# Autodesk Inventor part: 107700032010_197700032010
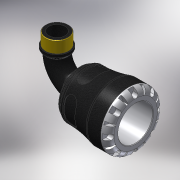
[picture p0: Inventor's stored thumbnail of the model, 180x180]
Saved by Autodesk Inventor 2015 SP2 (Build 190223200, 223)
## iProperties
Created: 2016-12
Part Number: 107700032010_197700032010
Material: PVC-Piping
Description: PLASSON 90° ELBOW WITH MALE INTEGRAL BRASS 32X1" SERIES 1
Document SubType Name: Modeling
Designer: KIM
Mass: 664.223 g
Surface Area: 733.008 cm^2
Volume: 474.445 cm^3
Density: 1.4 g/cm^3
Appearance: Black Cast
Author: KIM
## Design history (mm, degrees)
derived "1077.ipt"
feature "Solid1::1077.ipt"
tag "TaggingFeature1"
body "Solid1"
other parameters: "d1" = 22.68, "d2" = 32, "d4" = 58, "d8" = 49.3, "d13" = 7.2, "d14" = 7.2, "d15" = 0, "d17" = 360 deg, "d19" = 8 deg, "d20" = 0.64, "d21" = 0.64, "d22" = 8 deg, "d24" = 0, "d26" = 360 deg, "d33" = 5.8, "d43" = 45.24, "d51" = 0.58, "d54" = 11.2, "d55" = 7.04, "d57" = 14.112, "d58" = 0, "d74" = 0, "d78" = 54, "d82" = 0.64, "d115" = 360 deg, "d207" = 90 deg, "d228" = 9.52, "d247" = 1.16, "d248" = 3.24, "d268" = 27.115, "d269" = 3.24, "d270" = 81, "d276" = 33.249, "d277" = 17.5, "d278" = 36.5739, "d279" = 82, "d280" = 22.75, "d281" = 4.98735, "d283" = 29.9241, "d286" = 0, "d287" = 0, "d288" = 23.2743, "d290" = 7.65795, "d292" = 30 deg, "d294" = 3.3249, "d296" = 30 deg, "d_" = 32, "E_" = 58, "l_" = 54, "A_" = 81, "A_1" = 82, "l_2" = 17.5, "R_" = 33.249, "d9" = 9, "d11" = 58, "d289" = 23.2743
